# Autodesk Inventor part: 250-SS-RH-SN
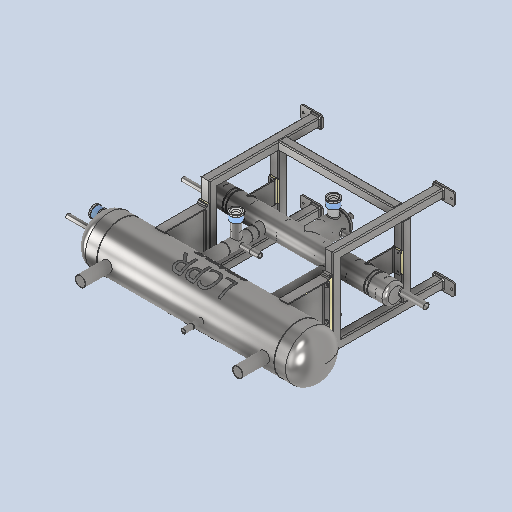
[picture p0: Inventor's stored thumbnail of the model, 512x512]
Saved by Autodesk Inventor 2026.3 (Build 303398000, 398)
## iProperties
Created: 2026-05
Part Number: 250-SS-RH-SN
Material: Generic
Document SubType Name: Modeling
Designer: rva
Density: 1 g/cm^3
Appearance: Default
Author: rva
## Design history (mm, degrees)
derived "250-SS-RH-SN.iam"
body "Solid1"
node "LCPR-SS-100- Sub Cooler-RH.iam:1::ISO 5251 Equal Tee DN100 3"
node "LCPR-SS-100- Sub Cooler-RH.iam:1::SS-100-14 hole Sub Cooler "
node "LCPR-SS-100- Sub Cooler-RH.iam:1::SS-100-14 hole Sub Cooler "
node "LCPR-SS-100- Sub Cooler-RH.iam:1::100 mm Subcooler Leg.ipt:1"
node "LCPR-SS-100- Sub Cooler-RH.iam:1::LCPR-SS-100 Blank Plate.ip"
node "LCPR-SS-100- Sub Cooler-RH.iam:1::100 mm Subcooler Leg.ipt:2"
node "LCPR-SS-100- Sub Cooler-RH.iam:1::1-2 Inch NPT Socket - SS.i"
node "LCPR-SS-100- Sub Cooler-RH.iam:1::H1100-R.ipt:1"
node "LCPR-SS-100- Sub Cooler-RH.iam:1::H1100-R.ipt:2"
node "LCPR-SS-100- Sub Cooler-RH.iam:1::1-2 Inch NPT Socket - SS.i"
node "LCPR-SS-100- Sub Cooler-RH.iam:1::1-2 Inch NPT Socket - SS.i"
node "LCPR-SS-100- Sub Cooler-RH.iam:1::Welds"
node "LCPR-SS-250-Frame Assembly.iam:2::LCPR-SS-250-120 x 70 Frame"
node "LCPR-SS-250-Frame Assembly.iam:2::LCPR-SS-250-120 x 70 Frame"
node "LCPR-SS-250-Frame Assembly.iam:2::LCPR-SS-250-120 x 70 Frame"
node "LCPR-SS-250-Frame Assembly.iam:2::LCPR-SS-250-120 x 70 Frame"
node "LCPR-SS-250-Frame Assembly.iam:2::Welds"
node "Nylon Heat Tranfer Spacer 276.5x50.ipt:1"
node "Nylon Heat Tranfer Spacer 276.5x50.ipt:2"
node "AS 1111 - Metric M10 x 80:1"
node "AS 1112 (4) - Metric M10:1"
node "AS 1237 (4.1) 10 mm:1"
node "AS 1237 (4.1) 10 mm:2"
node "AS 1111 - Metric M10 x 80:2"
node "AS 1112 (4) - Metric M10:2"
node "AS 1237 (4.1) 10 mm:3"
node "AS 1237 (4.1) 10 mm:4"
node "AS 1111 - Metric M10 x 80:3"
node "AS 1112 (4) - Metric M10:3"
node "AS 1237 (4.1) 10 mm:5"
node "AS 1237 (4.1) 10 mm:6"
node "AS 1111 - Metric M10 x 80:4"
node "AS 1112 (4) - Metric M10:4"
node "AS 1237 (4.1) 10 mm:7"
node "AS 1237 (4.1) 10 mm:8"
node "250-SS-SHELL-SN-WELD.iam:1::ASME B36.10M Pipe 10.75 x 0.165 "
node "250-SS-SHELL-SN-WELD.iam:1::LCPR-LOGO.ipt:1"
node "250-SS-SHELL-SN-WELD.iam:1::LCPR-SS-250 mm Dome End Cap.ipt:"
node "250-SS-SHELL-SN-WELD.iam:1::H1100-R.ipt:1"
node "250-SS-SHELL-SN-WELD.iam:1::LCPR-SS-250-Leg Assembly.iam:1::"
node "250-SS-SHELL-SN-WELD.iam:1::LCPR-SS-250-Leg Assembly.iam:2::"
node "250-SS-SHELL-SN-WELD.iam:1::LCPR-SS-250 mm Dome End Cap.ipt:"
node "Nylon Heat Tranfer Spacer 120x50.ipt:1"
node "Nylon Heat Tranfer Spacer 120x50.ipt:2"
node "250-SS-RH-SN.iam_Bodies"
